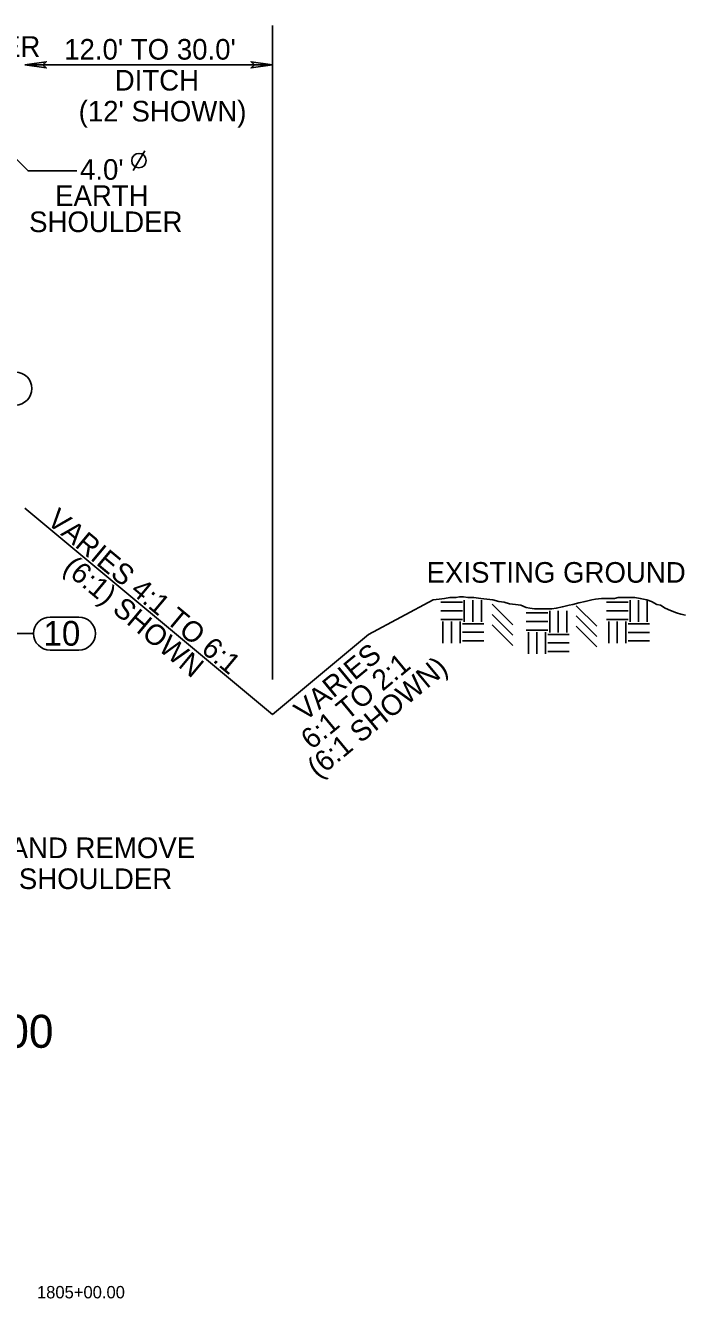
# Model space of a CAD drawing. Extents: x 2003207 to 2014043, y 843846 to 860154.
# Drawn here: x 2013712.4 to 2013744.4, y 844213.8 to 844275.5 of the extents above; entities that cross this region are included whole.
import ezdxf

# ---------------------------------------------------------------- set-up
doc = ezdxf.new("R2010")
doc.units = 0
for name, color, linetype in [('RD_EX_Road_txCode', 7, 'Continuous'), ('RD_QTY_PermVeg', 7, 'Continuous'), ('RD_SHT_TX', 7, 'Continuous'), ('RD_TX_Misc2', 7, 'Continuous'), ('RD_TX_TypSect', 7, 'Continuous'), ('RD_XS_ExGround', 7, 'Continuous')]:
    doc.layers.add(name, color=color, linetype=linetype)

msp = doc.modelspace()

# ---------------------------------------------------------------- linework, layer by layer
at = {"layer": 'RD_QTY_PermVeg'}
for p, q in [((2013712.409, 844252.136), (2013724.409, 844242.136)), ((2013724.409, 844242.136), (2013729.061, 844246.013))]:
    msp.add_line(p, q, dxfattribs=at)
at = {"layer": 'RD_TX_Misc2'}
for p, q in [((2013715.032, 844246.85), (2013713.632, 844246.85)), ((2013715.032, 844245.25), (2013713.632, 844245.25))]:
    msp.add_line(p, q, dxfattribs=at)
for centre, start, end in [((2013711.956, 844257.934), 270, 90), ((2013713.632, 844246.05), 90, 270), ((2013715.032, 844246.05), 270, 90)]:
    msp.add_arc(centre, 0.8, start, end, dxfattribs=at)
at = {"layer": 'RD_TX_TypSect'}
for p, q in [((2013724.409, 844243.833), (2013724.409, 844275.54)), ((2013712.409, 844273.633), (2013724.409, 844273.633)), ((2013717.659, 844268.515), (2013718.225, 844269.459))]:
    msp.add_line(p, q, dxfattribs=at)
for points in [[(2013712.409, 844273.633), (2013713.448, 844273.483), (2013713.288, 844273.633), (2013713.448, 844273.783)], [(2013724.409, 844273.633), (2013723.371, 844273.783), (2013723.531, 844273.633), (2013723.371, 844273.483)]]:
    msp.add_lwpolyline(points, close=True, dxfattribs=at)
for points in [[(2013714.927, 844268.485), (2013712.567, 844268.485), (2013710.409, 844270.629)], [(2013712.832, 844246.05), (2013711.166, 844246.05), (2013707.628, 844250.196)]]:
    msp.add_lwpolyline(points, dxfattribs=at)
msp.add_circle((2013717.942, 844268.987), 0.35, dxfattribs=at)
at = {"layer": 'RD_XS_ExGround'}
for p, q in [((2013732.195, 844247.685), (2013729.061, 844246.013)), ((2013733.609, 844247.573), (2013732.567, 844247.573)), ((2013733.705, 844247.67), (2013733.705, 844246.628)), ((2013734.122, 844247.67), (2013734.122, 844246.628)), ((2013734.538, 844247.67), (2013734.538, 844246.628)), ((2013736.061, 844246.479), (2013735.061, 844247.479)), ((2013740.129, 844246.405), (2013739.129, 844247.405)), ((2013741.635, 844247.568), (2013740.594, 844247.568)), ((2013741.732, 844247.665), (2013741.732, 844246.623)), ((2013742.149, 844247.665), (2013742.149, 844246.623)), ((2013742.565, 844247.665), (2013742.565, 844246.623)), ((2013733.609, 844247.156), (2013732.567, 844247.156)), ((2013736.061, 844245.979), (2013735.061, 844246.979)), ((2013737.745, 844247.054), (2013736.703, 844247.054)), ((2013737.841, 844247.151), (2013737.841, 844246.109)), ((2013738.258, 844247.151), (2013738.258, 844246.109)), ((2013738.675, 844247.151), (2013738.675, 844246.109)), ((2013740.129, 844245.905), (2013739.129, 844246.905)), ((2013741.635, 844247.151), (2013740.594, 844247.151)), ((2013733.609, 844246.739), (2013732.567, 844246.739)), ((2013732.671, 844246.635), (2013732.671, 844245.594)), ((2013733.088, 844246.635), (2013733.088, 844245.594)), ((2013733.505, 844246.635), (2013733.505, 844245.594)), ((2013734.65, 844246.531), (2013733.609, 844246.531)), ((2013736.061, 844245.479), (2013735.061, 844246.479)), ((2013737.745, 844246.638), (2013736.703, 844246.638)), ((2013737.745, 844246.221), (2013736.703, 844246.221)), ((2013740.129, 844245.405), (2013739.129, 844246.405)), ((2013741.635, 844246.735), (2013740.594, 844246.735)), ((2013740.698, 844246.631), (2013740.698, 844245.589)), ((2013741.115, 844246.631), (2013741.115, 844245.589)), ((2013741.531, 844246.631), (2013741.531, 844245.589)), ((2013742.677, 844246.526), (2013741.635, 844246.526)), ((2013734.65, 844246.114), (2013733.609, 844246.114)), ((2013734.65, 844245.698), (2013733.609, 844245.698)), ((2013736.807, 844246.117), (2013736.807, 844245.075)), ((2013737.224, 844246.117), (2013737.224, 844245.075)), ((2013737.641, 844246.117), (2013737.641, 844245.075)), ((2013738.787, 844246.013), (2013737.745, 844246.013)), ((2013738.787, 844245.596), (2013737.745, 844245.596)), ((2013742.677, 844246.11), (2013741.635, 844246.11)), ((2013742.677, 844245.693), (2013741.635, 844245.693)), ((2013738.787, 844245.179), (2013737.745, 844245.179))]:
    msp.add_line(p, q, dxfattribs=at)
msp.add_lwpolyline([(2013744.421, 844246.953), (2013744.202, 844246.989), (2013743.982, 844247.063), (2013743.689, 844247.172), (2013743.433, 844247.282), (2013743.213, 844247.429), (2013743.03, 844247.465), (2013742.774, 844247.612), (2013742.554, 844247.685), (2013742.225, 844247.758), (2013741.969, 844247.795), (2013741.676, 844247.795), (2013741.346, 844247.795), (2013741.163, 844247.795), (2013740.98, 844247.758), (2013740.761, 844247.758), (2013740.541, 844247.758), (2013740.358, 844247.758), (2013740.065, 844247.722), (2013739.882, 844247.685), (2013739.553, 844247.612), (2013739.26, 844247.539), (2013738.967, 844247.465), (2013738.784, 844247.429), (2013738.455, 844247.356), (2013738.162, 844247.282), (2013737.942, 844247.246), (2013737.759, 844247.246), (2013737.54, 844247.246), (2013737.32, 844247.246), (2013737.1, 844247.246), (2013736.881, 844247.282), (2013736.698, 844247.319), (2013736.441, 844247.429), (2013736.185, 844247.465), (2013735.892, 844247.502), (2013735.636, 844247.575), (2013735.38, 844247.612), (2013735.087, 844247.685), (2013734.794, 844247.722), (2013734.501, 844247.758), (2013734.172, 844247.795), (2013733.879, 844247.795), (2013733.66, 844247.832), (2013733.477, 844247.832), (2013733.294, 844247.795), (2013733.001, 844247.795), (2013732.744, 844247.758), (2013732.488, 844247.722), (2013732.195, 844247.685)], dxfattribs=at)

# ---------------------------------------------------------------- texts
at = {"layer": 'RD_EX_Road_txCode'}
msp.add_text('BLYRPD STA. 1797+69.52 TO STA. 1805+00.00', height=1.6, dxfattribs=at).set_placement((2013667.057, 844225.968))
at = {"layer": 'RD_SHT_TX'}
msp.add_text('1805+00.00', height=0.6, dxfattribs=at).set_placement((2013712.999, 844213.817))
at = {"layer": 'RD_TX_Misc2'}
msp.add_text('10', height=1.2, dxfattribs=at).set_placement((2013713.314, 844245.465))
at = {"layer": 'RD_TX_TypSect'}
for s, p in [("10.0' SHOULDER", (2013702.501, 844274.019)), ("12.0' TO 30.0'", (2013714.318, 844273.884)), ('DITCH', (2013716.767, 844272.384)), ("(12' SHOWN)", (2013715.019, 844270.884)), ("4.0'", (2013715.084, 844268.056)), ('EARTH', (2013713.879, 844266.788)), ('SHOULDER', (2013712.619, 844265.52)), ('EXISTING GROUND', (2013731.876, 844248.519)), ('SAWCUT AND REMOVE', (2013705.508, 844235.165)), ('EXISTING SHOULDER', (2013705.508, 844233.665))]:
    msp.add_text(s, height=1, dxfattribs=at).set_placement(p)
for s, rotation, p in [('VARIES 4:1 TO 6:1', 320.19443, (2013713.423, 844251.434)), (' (6:1) SHOWN', 320.19443, (2013713.918, 844249.371)), ('VARIES ', 39.5567, (2013725.98, 844241.761)), ('6:1 TO 2:1', 39.5567, (2013726.308, 844240.387)), ('(6:1 SHOWN)', 39.5567, (2013726.618, 844238.999))]:
    msp.add_text(s, height=1, rotation=rotation, dxfattribs=at).set_placement(p)

doc.saveas('drawing.dxf')
